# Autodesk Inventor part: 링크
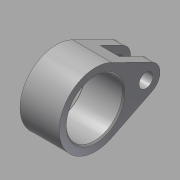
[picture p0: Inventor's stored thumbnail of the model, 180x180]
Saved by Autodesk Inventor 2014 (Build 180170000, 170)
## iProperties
Created: 2016-02
Part Number: 링크
Material: 강철, 연강
Document SubType Name: Modeling
Designer: test
Density: 1 g/cm^3
Appearance: 강철
Author: test
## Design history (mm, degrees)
sketch "스케치1"
  geometry: L1 (20.222, 4.479)-(5.778, 11.645); L2 (20.222, -4.479)-(5.778, -11.645); A1 r 13 centre (0, 0) between (5.778, 11.645) and (5.778, -11.645); A2 r 5 centre (18, 0) between (20.222, -4.479) and (20.222, 4.479); 1 further point
  constraints: 4 end point, 4 point on circle, 4 tangent, 2 centre point, 1 coincident, 1 horizontal alignment
  dimensions: "d0" = 18 distance of point (0, 0) A2.centre; "d1" = 13 radius of A1; "d2" = 5 radius of A2
extrude "돌출1" new body sketch "스케치1" stored distance "d3" = 14; taper "d4" = 0 deg
sketch "스케치2"
  geometry: C1 r 10 at (0, 0); 1 further point
  constraints: 1 centre point, 1 coincident
  dimensions: "d5" = 20 diameter of C1
extrude "돌출2" cut sketch "스케치2" stored distance "d6" = 14; taper "d7" = 0 deg
sketch "스케치3"
  geometry: C1 r 2.5 at (18, 0); A1 r 5 centre (18, 0) between (20.222, -4.479) and (20.222, 4.479) reference; 1 further point
  constraints: 1 centre point, 1 coincident
  dimensions: "d8" = 5 diameter of C1
extrude "돌출3" cut sketch "스케치3" stored distance "d9" = 14; taper "d10" = 0 deg
sketch "스케치4"
  geometry: L1 (20.222, -4.479)-(5.778, -11.645) reference; L2 (5.778, 11.645)-(20.222, 4.479) reference; L3 (12, 8.558)-(12, -8.558); C1 r 2.5 at (18, 0) reference; C2 r 10 at (0, 0) reference; A1 r 13 centre (0, 0) between (5.778, 11.645) and (5.778, -11.645) reference; A2 r 5 centre (18, 0) between (20.222, -4.479) and (20.222, 4.479) reference; 1 further point
  constraints: 2 end point, 2 point on line, 1 vertical
  dimensions: "d11" = 12 distance from line of L3 point (0, 0)
extrude "돌출4" cut sketch "스케치4" stored distance "d12" = 7; taper "d13" = 0 deg
chamfer "모따기1" distance "d14" = 0.5; stored, may be unused: second distance "d15" = 2, angle "d16" = 45 deg
node "솔리드1"
node "절단 모서리 투영1"
